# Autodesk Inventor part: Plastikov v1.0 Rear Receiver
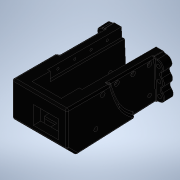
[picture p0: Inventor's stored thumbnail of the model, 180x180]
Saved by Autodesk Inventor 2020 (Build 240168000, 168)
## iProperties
Created: 2020-03
Part Number: Plastikov v1.0 Rear Receiver
Material: Steel
Document SubType Name: Modeling
Designer: Iv. Tr.
Density: 7.85 g/cm^3
Appearance: Default
Title: D:\Downloads\Plastikov-v1-0\STEP\Plastikov v0.9 Rear Receiver.stp
Author: johne
Sending System: Autodesk Inventor 2020
Preprocessor: ST-DEVELOPER v18
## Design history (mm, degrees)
feature "Solid2"
body "Solid1"
